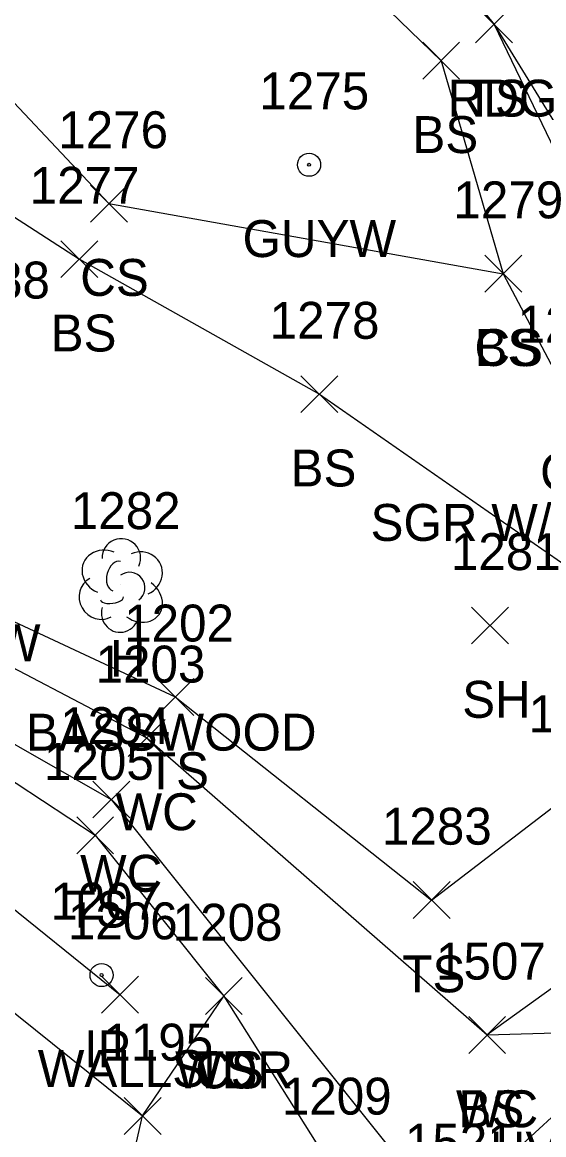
# Model space of a CAD drawing. Extents: x 1441651 to 1442140, y 243798 to 245625.
# Drawn here: x 1441999.2 to 1442027.4, y 245384.4 to 245444.6 of the extents above; entities that cross this region are included whole.
import ezdxf

# ---------------------------------------------------------------- set-up
doc = ezdxf.new("R2010")
doc.units = 0
for name, color, linetype in [('C_A', 7, 'Continuous'), ('C_C', 7, 'Continuous'), ('L_A', 7, 'Continuous'), ('L_C', 7, 'Continuous'), ('L_I', 7, 'Continuous'), ('L_TIC', 7, 'Continuous'), ('LAWA', 7, 'Continuous'), ('LAWE', 7, 'Continuous'), ('LELB', 7, 'Continuous'), ('LTD', 7, 'Continuous'), ('LWS', 7, 'Continuous'), ('M_A', 7, 'Continuous'), ('M_I', 7, 'Continuous'), ('MPIR', 7, 'Continuous'), ('P_A', 7, 'Continuous'), ('P_TIC', 7, 'Continuous'), ('PEU', 7, 'Continuous'), ('R_C', 7, 'Continuous'), ('U_A', 7, 'Continuous'), ('U_I', 7, 'Continuous'), ('UPGW', 7, 'Continuous')]:
    doc.layers.add(name, color=color, linetype=linetype)

msp = doc.modelspace()

# ---------------------------------------------------------------- linework, layer by layer
at = {"layer": 'L_TIC'}
for points in [[(1442023.733, 245443.52), (1442025.733, 245445.52)], [(1442025.733, 245443.52), (1442023.733, 245445.52)], [(1442020.867, 245441.546), (1442022.867, 245443.546)], [(1442022.867, 245441.546), (1442020.867, 245443.546)], [(1442002.87, 245433.808), (1442004.87, 245435.808)], [(1442004.87, 245433.808), (1442002.87, 245435.808)], [(1442001.268, 245430.797), (1442003.268, 245432.797)], [(1442003.268, 245430.797), (1442001.268, 245432.797)], [(1442024.23, 245430.01), (1442026.23, 245432.01)], [(1442026.23, 245430.01), (1442024.23, 245432.01)], [(1442024.23, 245430.01), (1442026.23, 245432.01)], [(1442026.23, 245430.01), (1442024.23, 245432.01)], [(1442014.267, 245423.484), (1442016.267, 245425.484)], [(1442016.267, 245423.484), (1442014.267, 245425.484)], [(1442023.518, 245410.952), (1442025.518, 245412.952)], [(1442025.518, 245410.952), (1442023.518, 245412.952)], [(1442006.462, 245407.084), (1442008.462, 245409.084)], [(1442008.462, 245407.084), (1442006.462, 245409.084)], [(1442004.916, 245404.86), (1442006.916, 245406.86)], [(1442006.916, 245404.86), (1442004.916, 245406.86)], [(1442002.996, 245401.527), (1442004.996, 245403.527)], [(1442004.996, 245401.527), (1442002.996, 245403.527)], [(1442002.121, 245399.589), (1442004.121, 245401.589)], [(1442004.121, 245399.589), (1442002.121, 245401.589)], [(1442020.352, 245396.079), (1442022.352, 245398.079)], [(1442022.352, 245396.079), (1442020.352, 245398.079)], [(1442003.469, 245390.951), (1442005.469, 245392.951)], [(1442005.469, 245390.951), (1442003.469, 245392.951)], [(1442009.091, 245390.874), (1442011.091, 245392.874)], [(1442011.091, 245390.874), (1442009.091, 245392.874)], [(1442009.091, 245390.874), (1442011.091, 245392.874)], [(1442011.091, 245390.874), (1442009.091, 245392.874)], [(1442009.091, 245390.874), (1442011.091, 245392.874)], [(1442011.091, 245390.874), (1442009.091, 245392.874)], [(1442023.361, 245388.769), (1442025.361, 245390.769)], [(1442025.361, 245388.769), (1442023.361, 245390.769)], [(1442023.361, 245388.769), (1442025.361, 245390.769)], [(1442025.361, 245388.769), (1442023.361, 245390.769)], [(1442004.692, 245384.381), (1442006.692, 245386.381)], [(1442006.692, 245384.381), (1442004.692, 245386.381)], [(1442004.692, 245384.381), (1442006.692, 245386.381)], [(1442006.692, 245384.381), (1442004.692, 245386.381)]]:
    msp.add_lwpolyline(points, dxfattribs=at)
at = {"layer": 'LAWA'}
msp.add_lwpolyline([(1441938.824, 245423.156), (1441966.589, 245419.586), (1441980.426, 245407.309), (1441994.994, 245393.975), (1442005.692, 245385.381), (1442010.091, 245391.874), (1442016.012, 245382.455), (1442013.066, 245379.249), (1442007.394, 245367.363), (1442001.156, 245351.178), (1441996.637, 245344.411), (1441988.517, 245326.607)], dxfattribs=at)
at = {"layer": 'LAWE'}
for points in [[(1441907.704, 245568.198), (1441910.354, 245545.097), (1441926.401, 245522.195), (1441938.487, 245498.109), (1441943.431, 245489.962), (1441943.382, 245477.871), (1441945.819, 245463.28), (1441949.518, 245451.716), (1441958.04, 245451.396), (1441967.21, 245432.067), (1441993.811, 245408.343), (1442003.996, 245402.527), (1442022.028, 245379.959)], [(1441911.342, 245568.336), (1441913.54, 245547.368), (1441930.794, 245525.129), (1441943.112, 245500.641), (1441948.928, 245491.303), (1441946.177, 245479.068), (1441949.055, 245463.199), (1441952.693, 245455.284), (1441960.253, 245454.331), (1441970.926, 245435.223), (1441995.301, 245411.435), (1442005.916, 245405.86), (1442024.361, 245389.769), (1442032.995, 245390.022)], [(1442099.331, 245492.7), (1442082.175, 245474.825), (1442073.962, 245459.556), (1442071.044, 245454.669), (1442067.5, 245447.08), (1442064.769, 245439.016), (1442060.82, 245433.995), (1442057.711, 245424.573), (1442056.016, 245422.421), (1442050.947, 245416.77), (1442046.422, 245406.149), (1442038.474, 245397.39), (1442032.995, 245390.022), (1442022.028, 245379.959), (1442015.438, 245373.014), (1442011.82, 245364.946), (1441999.311, 245341.928), (1441993.277, 245326.588), (1441983.696, 245301.797)]]:
    msp.add_lwpolyline(points, dxfattribs=at)
at = {"layer": 'LELB'}
for points in [[(1441923.447, 245583.224), (1441912.774, 245568.104), (1441914.394, 245547.708), (1441930.794, 245525.129), (1441946.539, 245502.48), (1441950.678, 245491.319), (1441947.348, 245479.457), (1441950.826, 245463.211), (1441954.445, 245457.195), (1441962.212, 245455.423), (1441972.577, 245437.756), (1441995.951, 245413.456), (1442007.462, 245408.084), (1442021.352, 245397.079), (1442029.302, 245403.168), (1442035.632, 245410.326), (1442039.926, 245412.912), (1442042.785, 245414.272)], [(1441906.336, 245567.87), (1441908.838, 245544.581), (1441926.401, 245522.195), (1441937.072, 245497.343), (1441939.983, 245490.583), (1441942.033, 245477.517), (1441944.373, 245463.316), (1441948.224, 245450.684), (1441957.161, 245448.976), (1441965.891, 245430.984), (1441993.118, 245407.16), (1442003.121, 245400.589), (1442010.091, 245391.874)], [(1442010.283, 245460.761), (1442024.733, 245444.52), (1442033.876, 245425.535)], [(1442004.083, 245459.771), (1442021.867, 245442.546), (1442025.23, 245431.01), (1442028.785, 245424.281), (1442039.926, 245412.912)], [(1441988.429, 245451.226), (1442003.87, 245434.808), (1442025.23, 245431.01), (1442028.785, 245424.281), (1442035.632, 245410.326)], [(1441982.227, 245444.744), (1442002.268, 245431.797), (1442015.267, 245424.484), (1442035.632, 245410.326)], [(1442042.32, 245408.629), (1442034.081, 245396.771), (1442024.361, 245389.769)], [(1441955.268, 245346.863), (1441965.214, 245362.626), (1441976.129, 245373.643), (1441994.994, 245393.975), (1441992.503, 245375.663), (1441988.382, 245359.287), (1441985.514, 245329.274), (1441996.05, 245349.813), (1442001.584, 245367.37), (1442003.863, 245377.365), (1442005.692, 245385.381), (1442010.091, 245391.874)]]:
    msp.add_lwpolyline(points, dxfattribs=at)
at = {"layer": 'LTD'}
msp.add_line((1442004.492, 245414.172), (1442004.492, 245414.172), dxfattribs=at)
msp.add_line((1442004.492, 245414.172), (1442004.492, 245414.172), dxfattribs=at)
msp.add_arc((1442004.539, 245415.606), 1.047, 335.52715, 180.95627, dxfattribs=at)
for centre, major_axis, ratio, start_param, end_param in [((1442003.701, 245414.839), (1.21, -0.512), 0.895232, 1.570796, 4.712389), ((1442005.534, 245414.756), (-1.141, -0.483), 0.949671, 1.570796, 4.712389), ((1442004.284, 245414.63), (-0.208, -0.792), 0.645439, 3.141593, 6.283185), ((1442004.992, 245414.005), (-0.5, 0.667), 0.989748, 3.141593, 6.283185), ((1442003.409, 245413.464), (0.584, -1.042), 0.959034, 3.141593, 6.283185), ((1442005.493, 245413.339), (-1.09, 0.792), 0.841452, 1.570796, 4.712389), ((1442004.034, 245413.422), (-0.625, -0.083), 0.423636, 0, 3.141593), ((1442004.493, 245412.672), (0.265, 1.061), 0.942809, 1.570796, 4.712389)]:
    msp.add_ellipse(centre, major_axis=major_axis, ratio=ratio, start_param=start_param, end_param=end_param, dxfattribs=at)
at = {"layer": 'LWS'}
msp.add_lwpolyline([(1441936.217, 245428.683), (1441968.253, 245423.319), (1441990.404, 245403.293), (1442004.469, 245391.951)], dxfattribs=at)
at = {"layer": 'MPIR'}
for radius in [0.625, 0.0833]:
    msp.add_circle((1442003.467, 245393.015), radius, dxfattribs=at)
at = {"layer": 'P_TIC'}
for points in [[(1442023.733, 245443.52), (1442025.733, 245445.52)], [(1442025.733, 245443.52), (1442023.733, 245445.52)]]:
    msp.add_lwpolyline(points, dxfattribs=at)
at = {"layer": 'PEU'}
msp.add_lwpolyline([(1441937.939, 245591.884), (1441953.89, 245562.719), (1441968.906, 245535.694), (1441984.797, 245506.977), (1441992.987, 245492.297), (1442013.076, 245458.975), (1442024.733, 245444.52), (1442043.134, 245414.629), (1442048.272, 245419.302), (1442053.641, 245424.38)], dxfattribs=at)
at = {"layer": 'UPGW'}
for radius in [0.625, 0.0833]:
    msp.add_circle((1442014.711, 245436.912), radius, dxfattribs=at)

# ---------------------------------------------------------------- texts
at = {"layer": 'C_A'}
msp.add_text('HVCTRL', height=2, dxfattribs=at).set_placement((1442024.503, 245382.534))
at = {"layer": 'C_C'}
msp.add_text('TIE =48.88', height=2, dxfattribs=at).set_placement((1441987.511, 245429.666))
at = {"layer": 'L_A'}
for s, p in [('TS', (1442023.143, 245439.52)), ('BS', (1442020.308, 245437.546)), ('CS', (1442002.311, 245429.808)), ('BS', (1442000.709, 245426.797)), ('CS', (1442023.671, 245426.01)), ('BS', (1442023.671, 245426.01)), ('BS', (1442013.708, 245419.484)), ('CS', (1442027.226, 245419.281)), ('H', (1442003.925, 245409.172)), ('SH', (1442023.006, 245406.952)), ('TS', (1442005.872, 245403.084)), ('WC', (1442004.223, 245400.86)), ('WC', (1442002.303, 245397.527)), ('TS', (1442001.53, 245395.589)), ('TS', (1442019.762, 245392.079)), ('WALLS', (1442000.012, 245386.951)), ('WDR', (1442007.454, 245386.874)), ('TS', (1442008.501, 245386.874)), ('CS', (1442008.532, 245386.874)), ('WC', (1442022.668, 245384.769)), ('BS', (1442022.802, 245384.769))]:
    msp.add_text(s, height=2, dxfattribs=at).set_placement(p)
at = {"layer": 'L_C'}
msp.add_text('2-M. BASSWOOD', height=2, dxfattribs=at).set_placement((1441993.272, 245405.172))
at = {"layer": 'L_I'}
for s, p in [('1276', (1442001.122, 245437.808)), ('1277', (1441999.575, 245434.797)), ('1279', (1442022.53, 245434.01)), ('1279', (1442022.53, 245434.01)), ('1278', (1442012.574, 245427.484)), ('1280', (1442026.005, 245427.281)), ('1280', (1442026.005, 245427.281)), ('1282', (1442001.799, 245417.172)), ('1281', (1442022.392, 245414.952)), ('1202', (1442004.691, 245411.084)), ('1203', (1442003.144, 245408.86)), ('1284', (1442026.609, 245406.168)), ('1204', (1442001.225, 245405.527)), ('1205', (1442000.349, 245403.589)), ('1283', (1442018.659, 245400.079)), ('1206', (1442001.642, 245394.951)), ('1208', (1442007.32, 245394.874)), ('1208', (1442007.32, 245394.874)), ('1208', (1442007.32, 245394.874)), ('1507', (1442021.589, 245392.769)), ('1507', (1442021.589, 245392.769)), ('1195', (1442003.566, 245388.381)), ('1195', (1442003.566, 245388.381)), ('1209', (1442013.233, 245385.455)), ('1521', (1442019.902, 245382.959)), ('1521', (1442019.902, 245382.959))]:
    msp.add_text(s, height=2, dxfattribs=at).set_placement(p)
at = {"layer": 'M_A'}
msp.add_text('IP', height=2, dxfattribs=at).set_placement((1442002.514, 245388.015))
at = {"layer": 'M_I'}
msp.add_text('1207', height=2, dxfattribs=at).set_placement((1442000.696, 245396.015))
at = {"layer": 'P_A'}
msp.add_text('RDG', height=2, dxfattribs=at).set_placement((1442022.221, 245439.52))
at = {"layer": 'R_C'}
msp.add_text('SGR W/ STEEL POST', height=2, dxfattribs=at).set_placement((1442018.041, 245416.535))
at = {"layer": 'U_A'}
for p in [(1442011.105, 245431.912), (1441991.842, 245410.008)]:
    msp.add_text('GUYW', height=2, dxfattribs=at).set_placement(p)
at = {"layer": 'U_I'}
msp.add_text('1275', height=2, dxfattribs=at).set_placement((1442012.019, 245439.912))

doc.saveas('drawing.dxf')
